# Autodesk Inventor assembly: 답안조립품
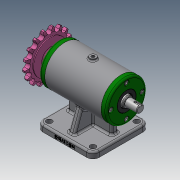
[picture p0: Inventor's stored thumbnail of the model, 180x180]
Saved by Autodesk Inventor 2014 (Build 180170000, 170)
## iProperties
Created: 2019-06
Part Number: 답안조립품
Document SubType Name: Assembly
Designer: net
Author: net
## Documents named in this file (11)
- C:\Users\net\Desktop\490604V1034\답안조립품.iam
- C:\Users\net\Desktop\490604V1034\답안본체.ipt
- C:\Users\net\Desktop\490604V1034\축.ipt
- C:\Users\net\Desktop\490604V1034\베어링 6203.ipt
- C:\Users\net\Desktop\490604V1034\커버.ipt
- C:\Users\net\Desktop\490604V1034\오일 실 17 30 5.ipt
- C:\Users\net\Desktop\490604V1034\스프로킷.ipt
- C:\Users\net\Desktop\490604V1034\키 4x4x12.ipt
- C:\Users\net\Desktop\490604V1034\평와셔.ipt
- C:\Users\net\Desktop\490604V1034\스프링와셔.ipt
- C:\Users\net\Desktop\490604V1034\볼트 M4.ipt
